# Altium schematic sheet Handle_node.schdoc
size 292 x 205 mm; Device: A_A4; Symbol: A_A4; Name: A_A4; Designator: A; @Project Name: HANDEL NODE; REV: 1.0; Date: 2026-01-13; Sheet: 1/1; Draw By: ocp21; Company: Your Company; Manufacturer Part: ?; Convert to PCB: yes; Add into BOM: yes; Origin Footprint: NONE; Unique ID: frame_lib_1
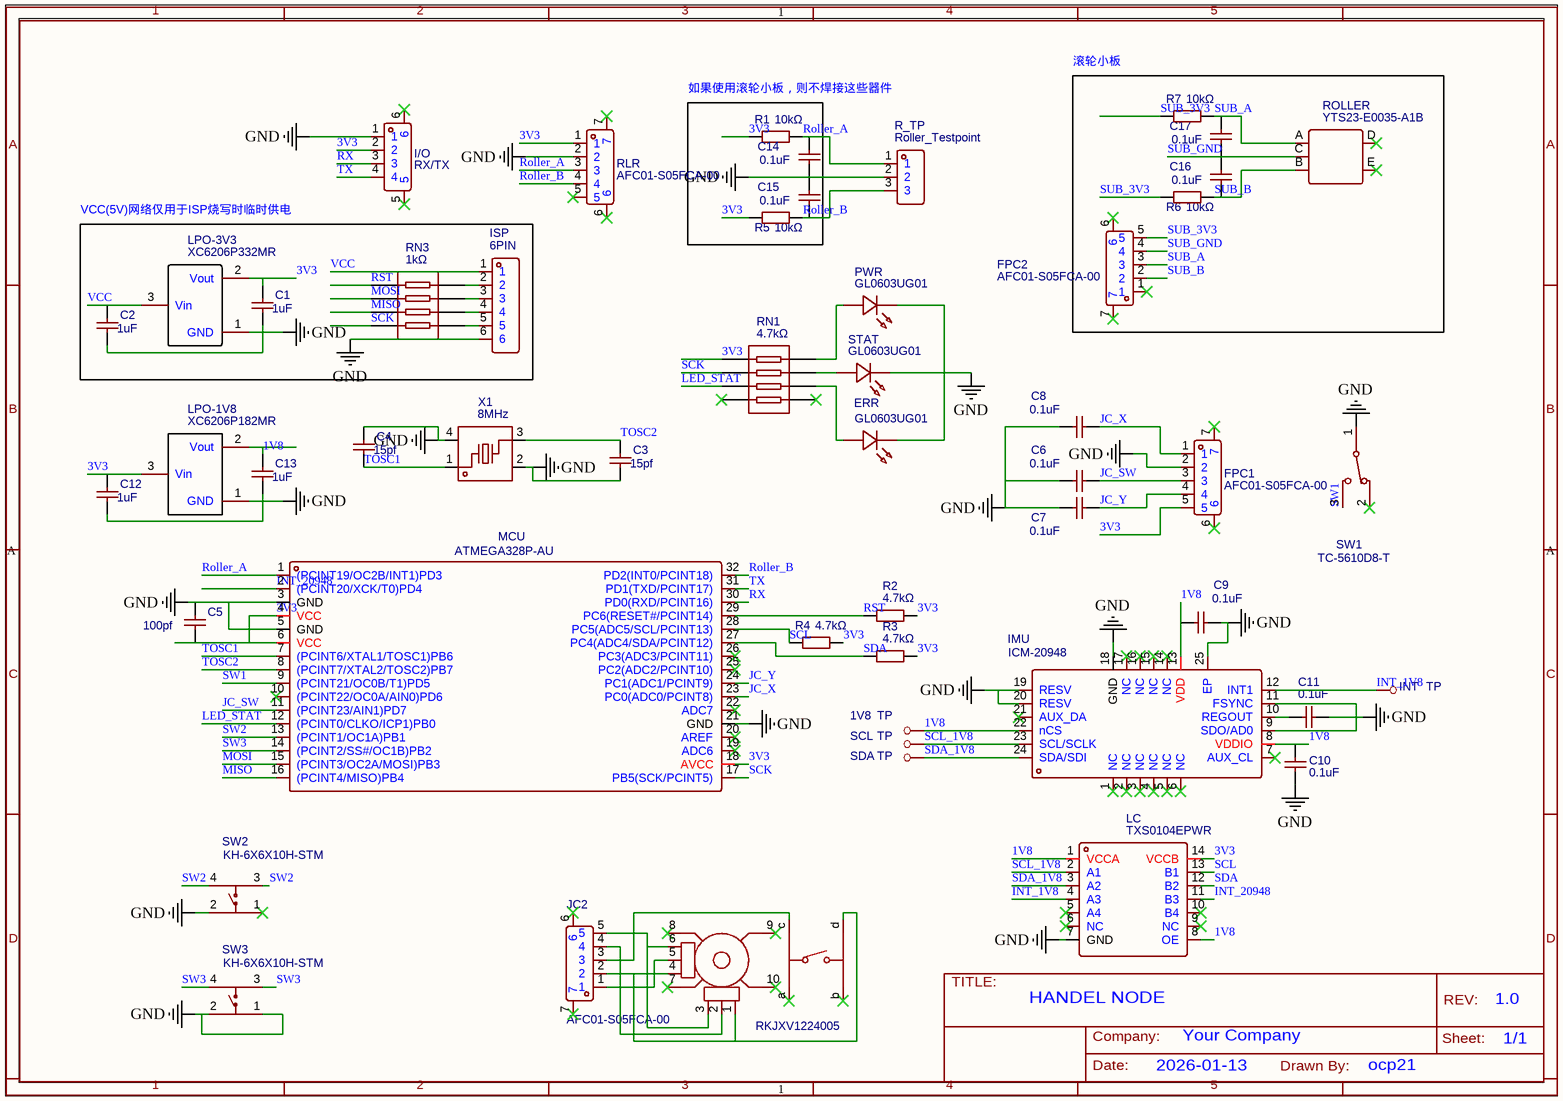
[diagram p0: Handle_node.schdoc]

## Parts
C1  1uF  [C0603]
C2  1uF  [C0603]
C3  15pf  [C0603]
C4  15pf  [C0603]
C5  100pf  [C0603]
C6  0.1uF  [C0603]
C7  0.1uF  [C0603]
C8  0.1uF  [C0603]
C9  0.1uF  [C0603]
C10  0.1uF  [C0603]
C11  0.1uF  [C0603]
C12  1uF  [C0603]
C13  1uF  [C0603]
C14  0.1uF  [C0603]
C15  0.1uF  [C0603]
C16  0.1uF  [C0603]
C17  0.1uF  [C0603]
ERR  GL0603UG01  [LED0603-RD]
FPC1  AFC01-S05FCA-00  [FPC-SMD_AFC01-S05FCA-00]
FPC2  AFC01-S05FCA-00  [FPC-SMD_AFC01-S05FCA-00]
I/O  RX/TX  [CONN-SMD_4P-P1.50_ZX-ZH1.5-4PWT]
IMU  ICM-20948  [QFN-24_L3.0-W3.0-P0.40-BL-EP]
ISP  6PIN  [HDR-TH_6P-P1.27-V-M]
JC2  AFC01-S05FCA-00  [FPC-SMD_AFC01-S05FCA-00]
LC  TXS0104EPWR  [TSSOP-14_L5.0-W4.4-P0.65-LS6.4-BL]
LPO-1V8  XC6206P182MR  [SOT-23-3_L2.9-W1.6-P1.90-LS2.8-BR]
LPO-3V3  XC6206P332MR  [SOT-23-3_L2.9-W1.6-P1.90-LS2.8-BR]
MCU  ATMEGA328P-AU  [TQFP-32_L7.0-W7.0-P0.80-LS9.0-BL]
PWR  GL0603UG01  [LED0603-RD]
R1  10kΩ  [R0603]
R2  4.7kΩ  [R0603]
R3  4.7kΩ  [R0603]
R4  4.7kΩ  [R0603]
R5  10kΩ  [R0603]
R6  10kΩ  [R0603]
R7  10kΩ  [R0603]
R_TP  Roller_Testpoint  [HDR-TH_3P-PZ1.0-UP1D-3A]
RLR  AFC01-S05FCA-00  [FPC-SMD_AFC01-S05FCA-00]
RN1  4.7kΩ  [RES-ARRAY-SMD_0603-8P-L3.2-W1.6-BL]
RN3  1kΩ  [RES-ARRAY-SMD_0603-8P-L3.2-W1.6-BL]
ROLLER  YTS23-E0035-A1B  [SW-SMD_YTS23-E0035-A1B]
STAT  GL0603UG01  [LED0603-RD]
SW1  TC-5610D8-T  [SW-TH_TC-5610D8-T]
SW2  KH-6X6X10H-STM  [SW-SMD_4P-L6.0-W6.0-P4.50-LS9.0-H10.0]
SW3  KH-6X6X10H-STM  [SW-SMD_4P-L6.0-W6.0-P4.50-LS9.0-H10.0]
SW4  RKJXV1224005  [SW-TH_RKJXV1224005]
T1  测试点  [0.5测试点]  (value not drawn)
T2  测试点  [0.5测试点]  (value not drawn)
T3  测试点  [0.5测试点]  (value not drawn)
T4  测试点  [0.5测试点]  (value not drawn)
X1  8MHz  [CRYSTAL-SMD_4P-L3.2-W2.5-BL]

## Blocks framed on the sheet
滚轮小板: C16 C17 FPC2 R6 R7 ROLLER
如果使用滚轮小板，则不焊接这些器件: C14 C15 R1 R5
VCC(5V)网络仅用于ISP烧写时临时供电: C1 C2 ISP LPO-3V3 RN3

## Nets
GND: C1.1 C2.1 C3.1 C4.2 C5.2 C6.2 C7.2 C8.2 C9.1 C10.2 C11.2 C12.1 C13.1 C14.2 C15.1 ERR.1(K) FPC1.2 I/O.1 IMU.9(SDO/AD0) IMU.11(FSYNC) IMU.18(GND) IMU.19(RESV) IMU.20(RESV) IMU.25(EP) ISP.6 LC.7(GND) LPO-1V8.1(GND) LPO-3V3.1(GND) MCU.3(GND) MCU.5(GND) MCU.21(GND) PWR.1(K) R_TP.2 RLR.2 STAT.1(K) SW1.1(COM) SW2.2(B) SW3.1(A) SW3.2(B) X1.2(GND) X1.4(GND)
1V8: C9.2 C10.1 C13.2 IMU.8(VDDIO) IMU.13(VDD) IMU.22(nCS) LC.1(VCCA) LC.8(OE) LPO-1V8.2(Vout) T1.1
3V3: C1.2 C5.1 C12.2 FPC1.5 I/O.2 LC.14(VCCB) LPO-1V8.3(Vin) LPO-3V3.2(Vout) MCU.4(VCC) MCU.6(VCC) MCU.18(AVCC) R1.1 R2.2 R3.2 R4.2 R5.1 RLR.1 RN1.1
INT_1V8: IMU.12(INT1) LC.4(A3) T4.1
INT_20948: LC.11(B3) MCU.2((PCINT20/XCK/T0)PD4)
JC_SW: C6.1 FPC1.3 MCU.11((PCINT23/AIN1)PD7)
JC_X: C8.1 FPC1.1 MCU.23(PC0(ADC0/PCINT8))
JC_Y: C7.1 FPC1.4 MCU.24(PC1(ADC1/PCINT9))
LED_STAT: MCU.12((PCINT0/CLKO/ICP1)PB0) RN1.3
MISO: MCU.16((PCINT4/MISO)PB4) RN3.3
MOSI: MCU.15((PCINT3/OC2A/MOSI)PB3) RN3.2
Roller_A: C14.1 MCU.1((PCINT19/OC2B/INT1)PD3) R1.2 R_TP.1 RLR.3
Roller_B: C15.2 MCU.32(PD2(INT0/PCINT18)) R5.2 R_TP.3 RLR.4
RST: MCU.29(PC6(RESET#/PCINT14)) R2.1 RN3.1
RX: I/O.3 MCU.30(PD0(RXD/PCINT16))
SCK: MCU.17(PB5(SCK/PCINT5)) RN1.2 RN3.4
SCL: LC.13(B1) MCU.28(PC5(ADC5/SCL/PCINT13)) R4.1
SCL_1V8: IMU.23(SCL/SCLK) LC.2(A1) T2.1
SDA: LC.12(B2) MCU.27(PC4(ADC4/SDA/PCINT12)) R3.1
SDA_1V8: IMU.24(SDA/SDI) LC.3(A2) T3.1
SUB_3V3: FPC2.5 R6.1 R7.1
SUB_A: C17.1 FPC2.3 R7.2 ROLLER.A
SUB_B: C16.2 FPC2.2 R6.2 ROLLER.B
SUB_GND: C16.1 C17.2 FPC2.4 ROLLER.C
SW1: MCU.9((PCINT21/OC0B/T1)PD5) SW1.3(NO)
SW2: MCU.13((PCINT1/OC1A)PB1) SW2.3(C) SW2.4(D)
SW3: MCU.14((PCINT2/SS#/OC1B)PB2) SW3.3(C) SW3.4(D)
TOSC1: C4.1 MCU.7((PCINT6/XTAL1/TOSC1)PB6) X1.1
TOSC2: C3.2 MCU.8((PCINT7/XTAL2/TOSC2)PB7) X1.3
TX: I/O.4 MCU.31(PD1(TXD/PCINT17))
VCC: C2.2 ISP.1 LPO-3V3.3(Vin)
NetC11_1: C11.1 IMU.10(REGOUT)
NetERR_2: ERR.2(A) RN1.6
NetISP_2: ISP.2 RN3.8
NetISP_3: ISP.3 RN3.7
NetISP_4: ISP.4 RN3.6
NetISP_5: ISP.5 RN3.5
NetJC2_1: JC2.1 JC2.5 SW4.3(A) SW4.5(DTA) SW4.6(B)
NetJC2_2: JC2.2 SW4.1(B) SW4.4(A) SW4.d
NetJC2_3: JC2.3 SW4.c
NetJC2_4: JC2.4 SW4.2(DTA)
NetPWR_2: PWR.2(A) RN1.8
NetRN1_7: RN1.7 STAT.2(A)

Not connected (* = marked no-connect by the designer): FPC1 6* 7*; FPC2 1* 6* 7*; I/O 5* 6*; IMU 1(NC)* 2(NC)* 3(NC)* 4(NC)* 5(NC)* 6(NC)* 7(AUX_CL)* 14(NC)* 15(NC)* 16(NC)* 17(NC)* 21(AUX_DA)*; JC2 6* 7*; LC 5(A4)* 6(NC)* 9(NC)* 10(B4)*; MCU 10((PCINT22/OC0A/AIN0)PD6)* 19(ADC6)* 20(AREF)* 22(ADC7)* 25(PC2(ADC2/PCINT10))* 26(PC3(ADC3/PCINT11))*; RLR 5* 6* 7*; RN1 4* 5*; ROLLER D* E*; SW1 2(NC)*; SW2 1(A)*; SW4 7(GND)* 8(GND)* 9(GND)* 10(GND)* a* b*

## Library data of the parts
C1 = CL05A105KP5NNNC: Manufacturer: SAMSUNG(三星); Convert to PCB: yes; UniqueId: gge463442e19da02213; ModelId: ac9b32e974bc448eab36b1293f859dcb; ModelName: C0603_L1.6-W0.8-H0.8; ModelTransform: v2:[39.37007874015748,0,0,0,39.37007874015748,0,0,0,39.37007874015748,0,0,0]
C2 = CL05A105KP5NNNC: Manufacturer: SAMSUNG(三星); Convert to PCB: yes; UniqueId: gge7c9095b5e9efb690; ModelId: ac9b32e974bc448eab36b1293f859dcb; ModelName: C0603_L1.6-W0.8-H0.8; ModelTransform: v2:[39.37007874015748,0,0,0,39.37007874015748,0,0,0,39.37007874015748,0,0,0]
C3 = CL05A105KP5NNNC: Manufacturer: SAMSUNG(三星); Convert to PCB: yes; UniqueId: gge20398a884c195f1b; ModelId: ac9b32e974bc448eab36b1293f859dcb; ModelName: C0603_L1.6-W0.8-H0.8; ModelTransform: v2:[39.37007874015748,0,0,0,39.37007874015748,0,0,0,39.37007874015748,0,0,0]
C4 = CL05A105KP5NNNC: Manufacturer: SAMSUNG(三星); Convert to PCB: yes; UniqueId: ggefab90927b80e47a4; ModelId: ac9b32e974bc448eab36b1293f859dcb; ModelName: C0603_L1.6-W0.8-H0.8; ModelTransform: v2:[39.37007874015748,0,0,0,39.37007874015748,0,0,0,39.37007874015748,0,0,0]
C5 = CL05A105KP5NNNC: Manufacturer: SAMSUNG(三星); Convert to PCB: yes; UniqueId: gge2ba651aee9152ccb; ModelId: ac9b32e974bc448eab36b1293f859dcb; ModelName: C0603_L1.6-W0.8-H0.8; ModelTransform: v2:[39.37007874015748,0,0,0,39.37007874015748,0,0,0,39.37007874015748,0,0,0]
C6 = CL05A105KP5NNNC: Manufacturer: SAMSUNG(三星); Convert to PCB: yes; UniqueId: gge49fe93f7fb48ce81; ModelId: ac9b32e974bc448eab36b1293f859dcb; ModelName: C0603_L1.6-W0.8-H0.8; ModelTransform: v2:[39.37007874015748,0,0,0,39.37007874015748,0,0,0,39.37007874015748,0,0,0]
C7 = CL05A105KP5NNNC: Manufacturer: SAMSUNG(三星); Convert to PCB: yes; UniqueId: gge5836655ba45b8f9b; ModelId: ac9b32e974bc448eab36b1293f859dcb; ModelName: C0603_L1.6-W0.8-H0.8; ModelTransform: v2:[39.37007874015748,0,0,0,39.37007874015748,0,0,0,39.37007874015748,0,0,0]
C8 = CL05A105KP5NNNC: Manufacturer: SAMSUNG(三星); Convert to PCB: yes; UniqueId: gge325a73e30ff7c5d3; ModelId: ac9b32e974bc448eab36b1293f859dcb; ModelName: C0603_L1.6-W0.8-H0.8; ModelTransform: v2:[39.37007874015748,0,0,0,39.37007874015748,0,0,0,39.37007874015748,0,0,0]
C9 = CL05A105KP5NNNC: Manufacturer: SAMSUNG(三星); Convert to PCB: yes; UniqueId: ggeae15437abd8fcc1e; ModelId: ac9b32e974bc448eab36b1293f859dcb; ModelName: C0603_L1.6-W0.8-H0.8; ModelTransform: v2:[39.37007874015748,0,0,0,39.37007874015748,0,0,0,39.37007874015748,0,0,0]
C10 = CL05A105KP5NNNC: Manufacturer: SAMSUNG(三星); Convert to PCB: yes; UniqueId: gge834fd25607015e2d; ModelId: ac9b32e974bc448eab36b1293f859dcb; ModelName: C0603_L1.6-W0.8-H0.8; ModelTransform: v2:[39.37007874015748,0,0,0,39.37007874015748,0,0,0,39.37007874015748,0,0,0]
C11 = CL05A105KP5NNNC: Manufacturer: SAMSUNG(三星); Convert to PCB: yes; UniqueId: gge75f77dc0e488a6a8; ModelId: ac9b32e974bc448eab36b1293f859dcb; ModelName: C0603_L1.6-W0.8-H0.8; ModelTransform: v2:[39.37007874015748,0,0,0,39.37007874015748,0,0,0,39.37007874015748,0,0,0]
C12 = CL05A105KP5NNNC: Manufacturer: SAMSUNG(三星); Convert to PCB: yes; UniqueId: gge5ee5a3a873bee6ce; ModelId: ac9b32e974bc448eab36b1293f859dcb; ModelName: C0603_L1.6-W0.8-H0.8; ModelTransform: v2:[39.37007874015748,0,0,0,39.37007874015748,0,0,0,39.37007874015748,0,0,0]
C13 = CL05A105KP5NNNC: Manufacturer: SAMSUNG(三星); Convert to PCB: yes; UniqueId: gge019037ab4d9a8b93; ModelId: ac9b32e974bc448eab36b1293f859dcb; ModelName: C0603_L1.6-W0.8-H0.8; ModelTransform: v2:[39.37007874015748,0,0,0,39.37007874015748,0,0,0,39.37007874015748,0,0,0]
C14 = CL05A105KP5NNNC: Manufacturer: SAMSUNG(三星); Convert to PCB: yes; UniqueId: gge1cdfa3adb8c36abb; ModelId: ac9b32e974bc448eab36b1293f859dcb; ModelName: C0603_L1.6-W0.8-H0.8; ModelTransform: v2:[39.37007874015748,0,0,0,39.37007874015748,0,0,0,39.37007874015748,0,0,0]
C15 = CL05A105KP5NNNC: Manufacturer: SAMSUNG(三星); Convert to PCB: yes; UniqueId: gge2f19f86ea210a479; ModelId: ac9b32e974bc448eab36b1293f859dcb; ModelName: C0603_L1.6-W0.8-H0.8; ModelTransform: v2:[39.37007874015748,0,0,0,39.37007874015748,0,0,0,39.37007874015748,0,0,0]
C16 = CL05A105KP5NNNC: Manufacturer: SAMSUNG(三星); Convert to PCB: yes; UniqueId: gge11da71ff999c81b4; ModelId: ac9b32e974bc448eab36b1293f859dcb; ModelName: C0603_L1.6-W0.8-H0.8; ModelTransform: v2:[39.37007874015748,0,0,0,39.37007874015748,0,0,0,39.37007874015748,0,0,0]
C17 = CL05A105KP5NNNC: Manufacturer: SAMSUNG(三星); Convert to PCB: yes; UniqueId: gge317fe87ca3250dfc; ModelId: ac9b32e974bc448eab36b1293f859dcb; ModelName: C0603_L1.6-W0.8-H0.8; ModelTransform: v2:[39.37007874015748,0,0,0,39.37007874015748,0,0,0,39.37007874015748,0,0,0]
ERR = GL0603UG01: Manufacturer: Guiguang light(桂光光电); Convert to PCB: yes; UniqueId: gge8c8eeec15dbb3182; ModelId: 3c2caa1a3e7d4a5a87f46b87d898ef41; ModelTransform: v2:[39.37007874015748,0,0,0,39.37007874015748,0,0,0,39.37007874015748,0.001,-0.001,0]
FPC1 = AFC01-S05FCA-00: Manufacturer: JS(钜硕电子); Convert to PCB: yes; UniqueId: gge6da0a08dacc20bd3; ModelId: 2ffd2b96456946c691ee1566715954f7; ModelTransform: v2:[39.37007874015748,0,0,0,39.37007874015748,0,0,0,39.37007874015748,0,-51.772,0]
FPC2 = AFC01-S05FCA-00: Manufacturer: JS(钜硕电子); Convert to PCB: yes; UniqueId: ggeaefab5299d888d52; ModelId: 2ffd2b96456946c691ee1566715954f7; ModelTransform: v2:[39.37007874015748,0,0,0,39.37007874015748,0,0,0,39.37007874015748,0,-51.772,0]
I/O = ZX-ZH1.5-4PWT: Manufacturer: Megastar(兆星); Convert to PCB: yes; UniqueId: gge99a73c97da5aac1c; ModelId: 919a32195fe24ac4bff0cbe012986613; ModelTransform: v2:[39.37007874015748,0,0,0,39.37007874015748,0,0,0,39.37007874015748,-0.001,-26.023,0]
IMU = ICM-20948: Manufacturer: TDK InvenSense(应美盛); Convert to PCB: yes; UniqueId: ggeaa0135695a911375; ModelId: ee2e77f6ae6443fd8761dd68811b5307; ModelName: QFN-24_L3.0-W3.0-H0.9-P0.40-BL-EP; ModelTransform: v2:[2.410722045565656e-15,39.37007874015748,0,-39.37007874015748,2.410722045565656e-15,0,0,0,39.37007874015748,0,0,0]
ISP = PZ127V-11-06-H25: Manufacturer: XFCN(兴飞); Convert to PCB: yes; UniqueId: gge08f31e13f1fd5ad6; ModelId: 91a400a27efe4f9bb82f5bf66d80642e; ModelTransform: v2:[39.37007874015748,0,0,0,39.37007874015748,0,0,0,39.37007874015748,0,0,-118.11]
JC2 = AFC01-S05FCA-00: Manufacturer: JS(钜硕电子); Add into BOM: yes; 3D Model: 2ffd2b96456946c691ee1566715954f7; 3D Model Transform: v2:[39.37007874015748,0,0,0,39.37007874015748,0,0,0,39.37007874015748,0,-51.772,0]
LC = TXS0104EPWR: Manufacturer: TI(德州仪器); Convert to PCB: yes; UniqueId: ggeb46f9a0a3d9b6705; ModelId: 5377177da492449fa1a3111d646cac17; ModelName: TSSOP-14_L5.0-W4.4-H1.0-LS6.4-P0.65; ModelTransform: v2:[2.410722045565656e-15,39.37007874015748,0,-39.37007874015748,2.410722045565656e-15,0,0,0,39.37007874015748,0.001,0.001,0]
LPO-1V8 = XC6206P182MR: Manufacturer: TOREX(特瑞仕); Convert to PCB: yes; UniqueId: gge77bcaa2e139bacff; ModelId: cefd4596db214da394d9632b2b88f8f2; ModelName: SOT-23-3L_L2.9-W1.6-H1.1-LS2.8-P0.95; ModelTransform: v2:[2.410722045565656e-15,39.37007874015748,0,-39.37007874015748,2.410722045565656e-15,0,0,0,39.37007874015748,-0.001,-0.002,0]
LPO-3V3 = XC6206P332MR-G: Manufacturer: TOREX(特瑞仕); Convert to PCB: yes; UniqueId: gge8626a56430a94118; ModelId: cefd4596db214da394d9632b2b88f8f2; ModelName: SOT-23-3L_L2.9-W1.6-H1.1-LS2.8-P0.95; ModelTransform: v2:[2.410722045565656e-15,39.37007874015748,0,-39.37007874015748,2.410722045565656e-15,0,0,0,39.37007874015748,-0.001,-0.002,0]
MCU = ATMEGA328P-AU: Manufacturer: MICROCHIP(美国微芯); Convert to PCB: yes; UniqueId: gge3aafcb9c48049203; ModelId: 4d9f6c3430024506b87ce44b53201fc5; ModelName: TQFP-32_L7.0-W7.0-H1.2-LS9.0-P0.80; ModelTransform: v2:[2.410722045565656e-15,39.37007874015748,0,-39.37007874015748,2.410722045565656e-15,0,0,0,39.37007874015748,-0.039,0.079,0]
PWR = GL0603UG01: Manufacturer: Guiguang light(桂光光电); Convert to PCB: yes; UniqueId: gged3093af8e8325be6; ModelId: 3c2caa1a3e7d4a5a87f46b87d898ef41; ModelTransform: v2:[39.37007874015748,0,0,0,39.37007874015748,0,0,0,39.37007874015748,0.001,-0.001,0]
R1 = 0603WAF1002T5E: Manufacturer: UNI-ROYAL(厚声); Convert to PCB: yes; UniqueId: gge7776841feef4283f; ModelId: 6bd5cd867e9542ebae21caaf5d2d4c4d; ModelTransform: v2:[2.410722045565656e-15,39.37007874015748,0,-39.37007874015748,2.410722045565656e-15,0,0,0,39.37007874015748,0,0,0]
R2 = 0603WAF1002T5E: Manufacturer: UNI-ROYAL(厚声); Convert to PCB: yes; UniqueId: ggeaa9539d2d731f168; ModelId: 6bd5cd867e9542ebae21caaf5d2d4c4d; ModelTransform: v2:[2.410722045565656e-15,39.37007874015748,0,-39.37007874015748,2.410722045565656e-15,0,0,0,39.37007874015748,0,0,0]
R3 = 0603WAF1002T5E: Manufacturer: UNI-ROYAL(厚声); Convert to PCB: yes; UniqueId: gged2b0cb9eddcc8f8b; ModelId: 6bd5cd867e9542ebae21caaf5d2d4c4d; ModelTransform: v2:[2.410722045565656e-15,39.37007874015748,0,-39.37007874015748,2.410722045565656e-15,0,0,0,39.37007874015748,0,0,0]
R4 = 0603WAF1002T5E: Manufacturer: UNI-ROYAL(厚声); Convert to PCB: yes; UniqueId: ggef4926452c1d26292; ModelId: 6bd5cd867e9542ebae21caaf5d2d4c4d; ModelTransform: v2:[2.410722045565656e-15,39.37007874015748,0,-39.37007874015748,2.410722045565656e-15,0,0,0,39.37007874015748,0,0,0]
R5 = 0603WAF1002T5E: Manufacturer: UNI-ROYAL(厚声); Convert to PCB: yes; UniqueId: gge43df99346a7d82ee; ModelId: 6bd5cd867e9542ebae21caaf5d2d4c4d; ModelTransform: v2:[2.410722045565656e-15,39.37007874015748,0,-39.37007874015748,2.410722045565656e-15,0,0,0,39.37007874015748,0,0,0]
R6 = 0603WAF1002T5E: Manufacturer: UNI-ROYAL(厚声); Convert to PCB: yes; UniqueId: ggea45ac3fdc4a0772a; ModelId: 6bd5cd867e9542ebae21caaf5d2d4c4d; ModelTransform: v2:[2.410722045565656e-15,39.37007874015748,0,-39.37007874015748,2.410722045565656e-15,0,0,0,39.37007874015748,0,0,0]
R7 = 0603WAF1002T5E: Manufacturer: UNI-ROYAL(厚声); Convert to PCB: yes; UniqueId: ggebab3731d3c22d0e2; ModelId: 6bd5cd867e9542ebae21caaf5d2d4c4d; ModelTransform: v2:[2.410722045565656e-15,39.37007874015748,0,-39.37007874015748,2.410722045565656e-15,0,0,0,39.37007874015748,0,0,0]
R_TP = PZ1.0-UP1D-3A: Manufacturer: XYECONN(辛译); Convert to PCB: yes; UniqueId: gge4af2e875561904e0; ModelId: 51252e879da64b0c983deec2559769fd; ModelTransform: v2:[39.37007874015748,0,0,0,39.37007874015748,0,0,0,39.37007874015748,-0.001,-0.001,-78.74]
RLR = AFC01-S05FCA-00: Manufacturer: JS(钜硕电子); Convert to PCB: yes; UniqueId: gge74ebbdd61868947f; ModelId: 2ffd2b96456946c691ee1566715954f7; ModelTransform: v2:[39.37007874015748,0,0,0,39.37007874015748,0,0,0,39.37007874015748,0,-51.772,0]
RN1 = 4D03WGJ0472T5E: Manufacturer: UNI-ROYAL(厚声); Convert to PCB: yes; UniqueId: ggef91e798257f1cc52; ModelId: 551b3dd0a237409fa823f51b33d3f6d1; ModelName: R0603-8P_L3.2-W1.6-H0.6; ModelTransform: v2:[39.37007874015748,0,0,0,39.37007874015748,0,0,0,39.37007874015748,0,0,0]
RN3 = 4D03WGJ0102T5E: Manufacturer: UNI-ROYAL(厚声); Convert to PCB: yes; UniqueId: gge8cb3440d5222c71d; ModelId: 551b3dd0a237409fa823f51b33d3f6d1; ModelName: R0603-8P_L3.2-W1.6-H0.6; ModelTransform: v2:[39.37007874015748,0,0,0,39.37007874015748,0,0,0,39.37007874015748,0,0,0]
ROLLER = YTS23-E0035-A1B: Manufacturer: YIYUAN(怡远); Convert to PCB: yes; UniqueId: gge3442d68bb0c81f4e; ModelId: 6cd8edb1ff094d28a1b33dded2e3e756; ModelTransform: v2:[39.37007874015748,0,0,0,39.37007874015748,0,0,0,39.37007874015748,0,-4.922,-31.496]
STAT = GL0603UG01: Manufacturer: Guiguang light(桂光光电); Convert to PCB: yes; UniqueId: gge604c63b080174abb; ModelId: 3c2caa1a3e7d4a5a87f46b87d898ef41; ModelTransform: v2:[39.37007874015748,0,0,0,39.37007874015748,0,0,0,39.37007874015748,0.001,-0.001,0]
SW1 = TC-5610D8-T: Manufacturer: Yuandi(元迪); Convert to PCB: yes; UniqueId: gge6d9f53c5695e0487; ModelId: eb28942b584148b9a68a0b4b7e14cf03; ModelTransform: v2:[39.37007874015748,0,0,0,39.37007874015748,0,0,0,39.37007874015748,-27.559,-226.378,-157.48]
SW2 = KH-6X6X10H-STM: Manufacturer: kinghelm(金航标); Convert to PCB: yes; UniqueId: gge96e042e7f9c298e1; ModelId: a5fab179a2ec40eaa30380d730651982; ModelTransform: v2:[39.37007874015748,0,0,0,39.37007874015748,0,0,0,39.37007874015748,0,0,0]
SW3 = KH-6X6X10H-STM: Manufacturer: kinghelm(金航标); Convert to PCB: yes; UniqueId: ggee7e5dec2360f2adb; ModelId: a5fab179a2ec40eaa30380d730651982; ModelTransform: v2:[39.37007874015748,0,0,0,39.37007874015748,0,0,0,39.37007874015748,0,0,0]
SW4 = RKJXV1224005: 操纵杆复位 中央按动开关 适用于航模玩具遥控器电位器、3D摇杆PS4手柄游戏机、无人机摇杆电位器、工业控制器; Manufacturer: ALPSALPINE(阿尔卑斯阿尔派); AddInBom: yes; ModelId: d71267aa208e4a128cc15a7eb8740b010819f05c4eef4c71ace90d822a990e87; ModelTransform: 681.101,838.581,0,0,0,0,-5.905,-5.906,-86.614
T1 = 测试点: Convert to PCB: yes; UniqueId: gge054ef179ff76ef0a
T2 = 测试点: Convert to PCB: yes; UniqueId: ggeaf5c28524ff3264c
T3 = 测试点: Convert to PCB: yes; UniqueId: ggeebf4aeea3ff6550f
T4 = 测试点: Convert to PCB: yes; UniqueId: gge43d8b9bcbe39e8f8
X1 = X32258MOB4SI: Manufacturer: YXC(扬兴晶振); Convert to PCB: yes; UniqueId: gged9acb6b6c49e108c; ModelId: 02485e56ba8d4732a26526d2983fc729; ModelTransform: v2:[39.37007874015748,0,0,0,39.37007874015748,0,0,0,39.37007874015748,0.001,0.002,0]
